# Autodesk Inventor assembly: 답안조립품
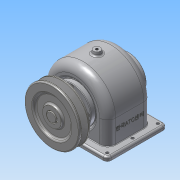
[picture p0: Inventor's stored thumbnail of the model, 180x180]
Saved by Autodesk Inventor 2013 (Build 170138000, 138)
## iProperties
Created: 2015-09
Part Number: 답안조립품
Document SubType Name: Assembly
Designer: Administrator
Author: Administrator
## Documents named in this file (14)
- C:\Users\Administrator\Desktop\450908V1013\답안조립품.iam
- C:\Users\Administrator\Desktop\450908V1013\1-본체.ipt
- C:\Users\Administrator\Desktop\450908V1013\뒤커버.ipt
- C:\Users\Administrator\Desktop\450908V1013\볼트 M3 x 8.ipt
- C:\Users\Administrator\Desktop\450908V1013\베어링 6203.ipt
- C:\Users\Administrator\Desktop\450908V1013\축.ipt
- C:\Users\Administrator\Desktop\450908V1013\키 - 6 x 6 x 22.ipt
- C:\Users\Administrator\Desktop\450908V1013\스퍼기어.ipt
- C:\Users\Administrator\Desktop\450908V1013\앞커버.ipt
- C:\Users\Administrator\Desktop\450908V1013\볼트 M3 x 10.ipt
- C:\Users\Administrator\Desktop\450908V1013\오일 실 17 32 8.ipt
- C:\Users\Administrator\Desktop\450908V1013\멈춤나사 - M4x10.ipt
- C:\Users\Administrator\Desktop\450908V1013\V-벨트풀리.ipt
- C:\Users\Administrator\Desktop\450908V1013\키 - 5 x 5 x 18.ipt
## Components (10 placed, 4 different names)
1. 1-본체:1
2. V-벨트풀리:1
3. ISO 4762 M3 x 8:1
4. ISO 4762 M3 x 8:2
5. ISO 4762 M3 x 8:3
6. ISO 4762 M3 x 8:4
7. ISO 4762 M3 x 10:1
8. ISO 4762 M3 x 10:2
9. ISO 4762 M3 x 10:3
10. ISO 4762 M3 x 10:4
